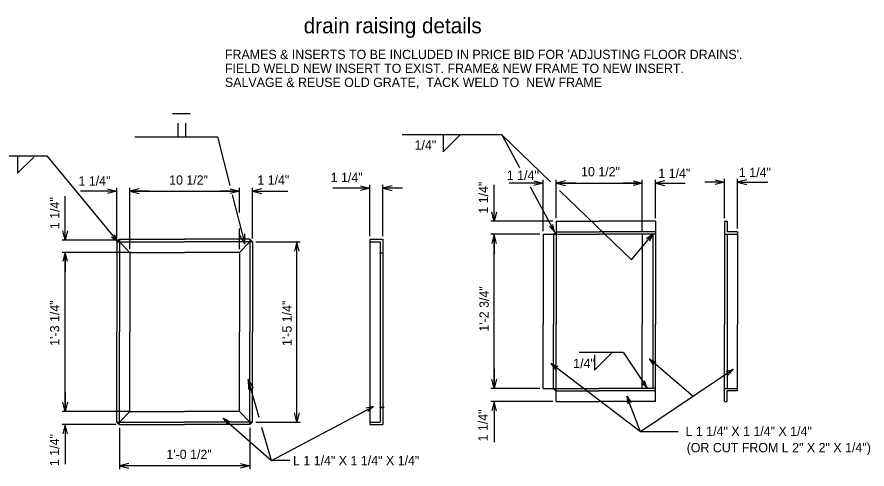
# Model space of a CAD drawing. Extents: x 973.2 to 1069.7, y 1484.4 to 1549.5.
# Drawn here: x 1004.28 to 1034.82, y 1515.51 to 1531.74 of the extents above; entities that cross this region are included whole.
import ezdxf

# ---------------------------------------------------------------- set-up
doc = ezdxf.new("R2010")
doc.units = 0
doc.layers.add('Level 2', color=7, linetype='Continuous')

msp = doc.modelspace()

# ---------------------------------------------------------------- linework, layer by layer
at = {"layer": 'Level 2'}
for p, q in [((1009.863, 1528.277), (1010.494, 1528.277)), ((1010.05, 1527.926), (1010.05, 1527.435)), ((1010.331, 1527.926), (1010.331, 1527.435)), ((1008.506, 1527.435), (1011.477, 1527.435)), ((1011.477, 1527.435), (1011.922, 1525.686)), ((1021.699, 1527.505), (1018.12, 1527.505)), ((1019.594, 1527.505), (1019.594, 1526.897)), ((1019.594, 1526.897), (1020.191, 1527.494)), ((1021.699, 1527.505), (1022.333, 1526.339)), ((1021.699, 1527.505), (1023.448, 1525.817)), ((1003.734, 1526.756), (1005.349, 1526.756)), ((1004.295, 1526.756), (1004.295, 1526.125)), ((1004.295, 1526.125), (1004.881, 1526.71)), ((1005.349, 1526.756), (1007.898, 1523.669)), ((1029.697, 1524.519), (1029.697, 1525.923)), ((1030.166, 1524.144), (1030.166, 1525.923)), ((1007.861, 1523.778), (1007.861, 1525.605)), ((1008.33, 1523.403), (1008.33, 1525.605)), ((1012.267, 1524.722), (1012.267, 1525.605)), ((1012.736, 1523.778), (1012.736, 1525.605)), ((1016.953, 1523.872), (1016.953, 1525.711)), ((1017.422, 1523.872), (1017.422, 1525.711)), ((1021.418, 1524.402), (1021.418, 1525.707)), ((1023.182, 1525.77), (1021.964, 1525.77)), ((1022.714, 1525.638), (1023.594, 1524.02)), ((1023.182, 1524.05), (1023.182, 1525.887)), ((1023.651, 1524.519), (1023.651, 1525.887)), ((1024.354, 1525.77), (1023.651, 1525.77)), ((1023.651, 1525.77), (1026.744, 1525.77)), ((1026.744, 1525.77), (1026.041, 1525.77)), ((1026.744, 1524.05), (1026.744, 1525.887)), ((1027.213, 1524.519), (1027.213, 1525.887)), ((1027.213, 1525.77), (1028.284, 1525.77)), ((1029.697, 1525.806), (1028.994, 1525.806)), ((1030.166, 1525.806), (1031.25, 1525.806)), ((1006.011, 1523.724), (1006.011, 1525.299)), ((1007.861, 1525.488), (1006.555, 1525.488)), ((1009.033, 1525.488), (1008.33, 1525.488)), ((1008.33, 1525.488), (1012.267, 1525.488)), ((1012.267, 1525.488), (1011.564, 1525.488)), ((1012.007, 1525.351), (1012.459, 1523.575)), ((1012.736, 1525.488), (1014.005, 1525.488)), ((1016.953, 1525.594), (1015.62, 1525.594)), ((1018.125, 1525.594), (1017.422, 1525.594)), ((1023.771, 1525.506), (1026.354, 1523.014)), ((1023.534, 1524.402), (1021.301, 1524.402)), ((1023.651, 1524.402), (1025.197, 1524.402)), ((1023.651, 1524.402), (1023.651, 1520.699)), ((1027.213, 1524.402), (1025.197, 1524.402)), ((1027.213, 1524.402), (1027.213, 1520.699)), ((1029.697, 1524.402), (1029.697, 1520.699)), ((1029.697, 1524.402), (1029.792, 1524.402)), ((1029.791, 1524.402), (1029.791, 1524.027)), ((1012.267, 1523.403), (1012.267, 1524.137)), ((1023.594, 1524.02), (1023.406, 1524.225)), ((1023.594, 1524.02), (1023.524, 1524.289)), ((1007.898, 1523.669), (1007.674, 1523.834)), ((1007.898, 1523.669), (1007.778, 1523.92)), ((1012.459, 1523.575), (1012.283, 1523.902)), ((1012.459, 1523.575), (1012.458, 1523.946)), ((1023.065, 1523.933), (1021.301, 1523.933)), ((1021.418, 1518.402), (1021.418, 1523.933)), ((1021.418, 1523.933), (1021.418, 1523.23)), ((1023.182, 1523.933), (1025.197, 1523.933)), ((1023.182, 1523.933), (1023.182, 1520.699)), ((1023.557, 1523.933), (1023.651, 1524.027)), ((1023.557, 1523.933), (1023.557, 1520.699)), ((1023.569, 1523.934), (1023.649, 1524.014)), ((1023.581, 1523.933), (1023.649, 1524.001)), ((1023.597, 1523.936), (1023.648, 1523.986)), ((1023.609, 1523.934), (1023.651, 1523.976)), ((1023.618, 1523.936), (1023.65, 1523.968)), ((1023.64, 1523.937), (1023.649, 1523.946)), ((1023.651, 1524.027), (1025.197, 1524.027)), ((1027.213, 1524.027), (1025.197, 1524.027)), ((1027.213, 1523.933), (1025.197, 1523.933)), ((1026.354, 1523.014), (1027.119, 1523.933)), ((1026.744, 1523.933), (1026.744, 1520.699)), ((1027.119, 1523.933), (1026.895, 1523.769)), ((1027.119, 1523.933), (1026.999, 1523.682)), ((1027.119, 1523.933), (1027.119, 1518.402)), ((1029.697, 1523.933), (1030.166, 1523.933)), ((1030.166, 1524.027), (1029.791, 1524.027)), ((1029.791, 1523.933), (1029.791, 1518.402)), ((1030.166, 1524.027), (1030.166, 1520.699)), ((1007.828, 1523.724), (1005.894, 1523.724)), ((1007.861, 1523.661), (1007.955, 1523.755)), ((1007.861, 1523.661), (1007.861, 1520.427)), ((1007.861, 1523.661), (1010.299, 1523.661)), ((1007.87, 1523.661), (1007.95, 1523.746)), ((1007.954, 1523.742), (1007.877, 1523.668)), ((1007.877, 1523.664), (1007.955, 1523.734)), ((1007.891, 1523.668), (1007.951, 1523.716)), ((1007.899, 1523.664), (1007.954, 1523.708)), ((1007.91, 1523.664), (1007.955, 1523.702)), ((1007.918, 1523.661), (1007.95, 1523.685)), ((1007.93, 1523.661), (1007.951, 1523.68)), ((1007.95, 1523.746), (1007.954, 1523.742)), ((1008.33, 1523.286), (1007.954, 1523.66)), ((1007.955, 1523.755), (1007.955, 1520.427)), ((1007.955, 1523.755), (1010.299, 1523.755)), ((1012.642, 1523.755), (1010.299, 1523.755)), ((1012.736, 1523.661), (1010.299, 1523.661)), ((1012.267, 1523.286), (1012.643, 1523.66)), ((1012.736, 1523.661), (1012.642, 1523.755)), ((1012.642, 1523.755), (1012.642, 1520.427)), ((1012.72, 1523.664), (1012.642, 1523.734)), ((1012.687, 1523.664), (1012.642, 1523.702)), ((1012.647, 1523.746), (1012.643, 1523.742)), ((1012.643, 1523.742), (1012.72, 1523.668)), ((1012.698, 1523.664), (1012.643, 1523.708)), ((1012.706, 1523.668), (1012.646, 1523.716)), ((1012.667, 1523.661), (1012.646, 1523.68)), ((1012.727, 1523.661), (1012.647, 1523.746)), ((1012.679, 1523.661), (1012.647, 1523.685)), ((1012.736, 1523.661), (1012.736, 1520.427)), ((1012.853, 1523.661), (1014.451, 1523.661)), ((1014.334, 1517.192), (1014.334, 1523.661)), ((1016.953, 1523.755), (1017.422, 1523.755)), ((1016.953, 1523.755), (1016.953, 1517.098)), ((1016.953, 1523.661), (1017.328, 1523.661)), ((1017.328, 1523.661), (1017.328, 1517.192)), ((1017.422, 1523.755), (1017.422, 1517.098)), ((1008.371, 1523.286), (1005.894, 1523.286)), ((1006.011, 1517.567), (1006.011, 1523.286)), ((1006.011, 1523.286), (1006.011, 1522.583)), ((1008.33, 1523.286), (1008.33, 1520.427)), ((1008.33, 1523.286), (1010.299, 1523.286)), ((1012.267, 1523.286), (1010.299, 1523.286)), ((1012.267, 1523.286), (1012.267, 1520.427)), ((1017.296, 1523.27), (1017.419, 1523.27)), ((1007.861, 1517.192), (1007.861, 1520.427)), ((1007.955, 1517.098), (1007.955, 1520.427)), ((1008.33, 1517.567), (1008.33, 1520.427)), ((1012.267, 1517.567), (1012.267, 1520.427)), ((1012.642, 1517.098), (1012.642, 1520.427)), ((1012.736, 1517.192), (1012.736, 1520.427)), ((1023.182, 1518.402), (1023.182, 1520.699)), ((1023.557, 1518.402), (1023.557, 1520.699)), ((1023.651, 1517.933), (1023.651, 1520.699)), ((1026.744, 1518.402), (1026.744, 1520.699)), ((1027.213, 1517.933), (1027.213, 1520.699)), ((1029.697, 1517.933), (1029.697, 1520.699)), ((1030.166, 1518.308), (1030.166, 1520.699)), ((1024.48, 1519.704), (1026.05, 1519.704)), ((1025.021, 1519.049), (1025.594, 1519.622)), ((1025.021, 1519.61), (1025.021, 1519.049)), ((1025.594, 1519.622), (1025.667, 1519.695)), ((1026.051, 1519.704), (1026.918, 1518.407)), ((1026.68, 1516.838), (1023.454, 1519.294)), ((1023.454, 1519.294), (1023.709, 1519.185)), ((1023.454, 1519.294), (1023.628, 1519.077)), ((1028.568, 1518.114), (1026.986, 1519.458)), ((1026.986, 1519.458), (1027.235, 1519.335)), ((1026.986, 1519.458), (1027.148, 1519.232)), ((1021.418, 1519.105), (1021.418, 1518.402)), ((1023.651, 1518.87), (1023.651, 1519.014)), ((1030.003, 1519.084), (1026.68, 1516.838)), ((1027.213, 1518.87), (1027.213, 1519.014)), ((1030.003, 1519.084), (1029.742, 1518.989)), ((1030.003, 1519.084), (1029.817, 1518.877)), ((1012.972, 1517.359), (1012.576, 1518.733)), ((1012.576, 1518.733), (1012.762, 1518.412)), ((1012.576, 1518.733), (1012.589, 1518.362)), ((1026.918, 1518.407), (1026.712, 1518.594)), ((1026.918, 1518.407), (1026.824, 1518.669)), ((1006.011, 1518.27), (1006.011, 1517.567)), ((1023.065, 1518.402), (1021.301, 1518.402)), ((1023.182, 1518.402), (1025.197, 1518.402)), ((1023.557, 1518.402), (1023.651, 1518.308)), ((1023.569, 1518.401), (1023.649, 1518.321)), ((1023.581, 1518.402), (1023.649, 1518.334)), ((1023.597, 1518.399), (1023.648, 1518.348)), ((1023.609, 1518.401), (1023.651, 1518.359)), ((1023.618, 1518.399), (1023.65, 1518.367)), ((1023.64, 1518.397), (1023.649, 1518.389)), ((1023.651, 1518.308), (1025.197, 1518.308)), ((1027.213, 1518.402), (1025.197, 1518.402)), ((1027.213, 1518.308), (1025.197, 1518.308)), ((1029.697, 1518.402), (1030.166, 1518.402)), ((1029.792, 1517.933), (1029.792, 1518.308)), ((1030.166, 1518.308), (1029.792, 1518.308)), ((1026.68, 1516.838), (1026.19, 1518.125)), ((1026.19, 1518.125), (1026.349, 1517.896)), ((1026.19, 1518.125), (1026.223, 1517.848)), ((1013.417, 1515.809), (1017.091, 1517.751)), ((1017.091, 1517.751), (1016.821, 1517.684)), ((1017.091, 1517.751), (1016.884, 1517.565)), ((1017.296, 1517.724), (1017.463, 1517.724)), ((1017.314, 1517.706), (1017.37, 1517.706)), ((1023.534, 1517.933), (1021.301, 1517.933)), ((1021.418, 1517.933), (1021.418, 1516.469)), ((1023.651, 1517.933), (1025.197, 1517.933)), ((1027.213, 1517.933), (1025.197, 1517.933)), ((1029.697, 1517.933), (1029.792, 1517.933)), ((1008.29, 1517.567), (1005.894, 1517.567)), ((1008.33, 1517.567), (1007.954, 1517.193)), ((1008.33, 1517.567), (1010.299, 1517.567)), ((1012.267, 1517.567), (1010.299, 1517.567)), ((1012.267, 1517.567), (1012.643, 1517.193)), ((1007.838, 1517.098), (1005.894, 1517.098)), ((1006.011, 1517.098), (1006.011, 1515.68)), ((1007.861, 1517.192), (1007.955, 1517.098)), ((1007.861, 1517.192), (1010.299, 1517.192)), ((1007.87, 1517.192), (1007.95, 1517.107)), ((1007.877, 1517.189), (1007.955, 1517.119)), ((1007.954, 1517.112), (1007.877, 1517.185)), ((1007.891, 1517.185), (1007.951, 1517.137)), ((1007.899, 1517.189), (1007.954, 1517.145)), ((1007.91, 1517.189), (1007.955, 1517.152)), ((1007.918, 1517.192), (1007.95, 1517.168)), ((1007.93, 1517.192), (1007.951, 1517.173)), ((1007.95, 1517.107), (1007.954, 1517.112)), ((1007.955, 1517.098), (1010.299, 1517.098)), ((1012.736, 1517.192), (1010.299, 1517.192)), ((1012.642, 1517.098), (1010.299, 1517.098)), ((1011.688, 1517.329), (1013.417, 1515.809)), ((1011.688, 1517.329), (1011.935, 1517.202)), ((1011.688, 1517.329), (1011.846, 1517.1)), ((1012.736, 1517.192), (1012.642, 1517.098)), ((1012.72, 1517.189), (1012.642, 1517.119)), ((1012.687, 1517.189), (1012.642, 1517.152)), ((1012.698, 1517.189), (1012.643, 1517.145)), ((1012.643, 1517.112), (1012.72, 1517.185)), ((1012.647, 1517.107), (1012.643, 1517.112)), ((1012.667, 1517.192), (1012.646, 1517.173)), ((1012.706, 1517.185), (1012.646, 1517.137)), ((1012.679, 1517.192), (1012.647, 1517.168)), ((1012.727, 1517.192), (1012.647, 1517.107)), ((1012.853, 1517.192), (1014.451, 1517.192)), ((1016.953, 1517.192), (1017.328, 1517.192)), ((1016.953, 1517.098), (1017.422, 1517.098)), ((1007.955, 1516.981), (1007.955, 1515.505)), ((1012.642, 1516.981), (1012.642, 1515.505)), ((1013.417, 1515.809), (1013.075, 1516.998)), ((1028.038, 1516.838), (1026.68, 1516.838)), ((1012.642, 1515.622), (1007.955, 1515.622)), ((1014.073, 1515.809), (1013.417, 1515.809))]:
    msp.add_line(p, q, dxfattribs=at)
for points in [[(1016.62, 1525.677), (1016.953, 1525.594), (1016.62, 1525.51)], [(1017.755, 1525.677), (1017.422, 1525.594), (1017.755, 1525.51)], [(1022.848, 1525.853), (1023.182, 1525.77), (1022.848, 1525.687)], [(1023.984, 1525.853), (1023.651, 1525.77), (1023.984, 1525.687)], [(1026.411, 1525.853), (1026.744, 1525.77), (1026.411, 1525.687)], [(1027.546, 1525.853), (1027.213, 1525.77), (1027.546, 1525.687)], [(1029.364, 1525.89), (1029.697, 1525.806), (1029.364, 1525.723)], [(1030.499, 1525.89), (1030.166, 1525.806), (1030.499, 1525.723)], [(1007.528, 1525.571), (1007.861, 1525.488), (1007.528, 1525.404)], [(1008.663, 1525.571), (1008.33, 1525.488), (1008.663, 1525.404)], [(1011.934, 1525.571), (1012.267, 1525.488), (1011.934, 1525.404)], [(1013.069, 1525.571), (1012.736, 1525.488), (1013.069, 1525.404)], [(1021.501, 1524.735), (1021.418, 1524.402), (1021.335, 1524.735)], [(1006.095, 1524.058), (1006.011, 1523.724), (1005.928, 1524.058)], [(1021.501, 1523.6), (1021.418, 1523.933), (1021.335, 1523.6)], [(1014.417, 1523.328), (1014.334, 1523.661), (1014.251, 1523.328)], [(1006.095, 1522.953), (1006.011, 1523.286), (1005.928, 1522.953)], [(1021.501, 1518.735), (1021.418, 1518.402), (1021.335, 1518.735)], [(1006.095, 1517.901), (1006.011, 1517.567), (1005.928, 1517.901)], [(1021.501, 1517.599), (1021.418, 1517.933), (1021.335, 1517.599)], [(1014.417, 1517.526), (1014.334, 1517.192), (1014.251, 1517.526)], [(1006.095, 1516.765), (1006.011, 1517.098), (1005.928, 1516.765)], [(1008.288, 1515.706), (1007.955, 1515.622), (1008.288, 1515.539)], [(1012.309, 1515.706), (1012.642, 1515.622), (1012.309, 1515.539)]]:
    msp.add_lwpolyline(points, dxfattribs=at)

# ---------------------------------------------------------------- texts
for s, height, p in [('drain raising details', 0.555, (1014.578, 1531.153)), ("FRAMES & INSERTS TO BE INCLUDED IN PRICE BID FOR 'ADJUSTING FLOOR DRAINS'.", 0.33333, (1011.747, 1530.227)), ('FIELD WELD NEW INSERT TO EXIST. FRAME& NEW FRAME TO NEW INSERT.', 0.33333, (1011.747, 1529.727)), ('SALVAGE & REUSE OLD GRATE,  TACK WELD TO  NEW FRAME', 0.33333, (1011.747, 1529.227)), ('1/4"', 0.3333, (1018.561, 1526.971)), (' 1 1/4"', 0.3333, (1021.753, 1525.887)), (' 10 1/2"', 0.3333, (1024.419, 1526.016)), (' 1 1/4"', 0.3333, (1027.196, 1525.956)), (' 1 1/4"', 0.3333, (1030.09, 1525.988)), (' 1 1/4"', 0.3333, (1006.359, 1525.686)), (' 10 1/2"', 0.3333, (1009.618, 1525.717)), (' 1 1/4"', 0.3333, (1012.786, 1525.718)), (' 1 1/4"', 0.3333, (1015.423, 1525.811)), ('1/4"', 0.3333, (1024.261, 1519.129)), ('L 1 1/4" X 1 1/4" X 1/4"', 0.33333, (1028.298, 1516.694)), ('(OR CUT FROM L 2" X 2" X 1/4")', 0.33333, (1028.339, 1516.107)), ('1\'-0 1/2"', 0.3333, (1009.641, 1515.866)), ('L 1 1/4" X 1 1/4" X 1/4"', 0.33333, (1014.193, 1515.641))]:
    msp.add_text(s, height=height, dxfattribs=at).set_placement(p)
for s, p in [('1 1/4"', (1021.203, 1524.676)), (' 1 1/4"', (1005.8, 1523.993)), ('1\'-2 3/4"', (1021.225, 1520.437)), ('1\'-3 1/4"', (1005.795, 1519.931)), ('1\'-5 1/4"', (1014.145, 1519.921)), (' 1 1/4"', (1021.188, 1516.372)), (' 1 1/4"', (1005.789, 1515.485))]:
    msp.add_text(s, height=0.3333, rotation=90, dxfattribs=at).set_placement(p)

doc.saveas('drawing.dxf')
